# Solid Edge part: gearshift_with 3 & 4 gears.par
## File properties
Author: vinurabandara
Template: iso metric part.par
Last saved by: Nimesh.N
Revision: 22
Application: Solid Edge
Density: 7833.000 kg/m^3
Accuracy: 0.990
Username: Nimesh.N
Material: Steel
Face Style: Steel
Fill Style: ANSI32(Steel)
Virtual Style: Machined steel
Grouping: Metals\Steel
LibraryName: Materials
Coef. of Thermal Exp: 1.3e-05
Thermal Conductivity: 32.0
Specific Heat: 481.0
Modulus of Elasticity: 199947953000.0
Poisson's Ratio: 0.29
Yield Stress: 262000766.0
Ultimate Stress: 358527364.0
Elongation: 0.0
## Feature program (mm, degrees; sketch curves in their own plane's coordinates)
sketch for "unnamed Protrusion 1" plane through (0, 0, 0) normal (0, -1, 0) x-axis (1, 0, 0)
  line (-20, 111) -> (20, 111)
  line (20, 111) -> (68.5807, 62.4193)
  line (68.5807, 18.3762) -> (68.5807, 62.4193)
  line (53.6089, 14.3645) -> (68.5807, 18.3762)
  line (-53.6089, 14.3645) -> (-68.5807, 18.3762)
  line (-68.5807, 18.3762) -> (-68.5807, 62.4193)
  line (-20, 111) -> (-68.5807, 62.4193)
extrude "unnamed Protrusion 1" add finite 10 along +normal
fillet "Round_1" radius 10
sketch for "ExtrudedProtrusion_4" plane through (0, -5, 111) normal (0, 0, 1) x-axis (0, 1, 0)
extrude "ExtrudedProtrusion_4" add finite 250 along +normal
rib "Rib_2"  Thickness = 15 mm
fillet "Round_2" radius 5
fillet "Round_3" radius 5
sketch for "ExtrudedCutout_2" plane through (0, 0, 292) normal (0, 0, 1) x-axis (1, 0, 0)
extrude "ExtrudedCutout_2" cut finite 83 along +normal  Profile_Plane1_Distance = 292 mm
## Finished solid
Body 1: solid body, 20 faces, 54 edges, 36 vertices.
  Faces by surface: plane 15, cylinder 5
  Edges by curve: line 44, circle 10
Bounding box of the edges (mm): 137.161 x 15.000 x 277.635, from (-68.5807, -15, 14.3645) to (68.5807, 0, 292).
Cylindrical faces by radius (mm): R5 x2, R10 x2, R55.5 x1
Planar faces by outward normal: +x 2, +y 1, +z 3, -x 2, -y 2, oblique 5
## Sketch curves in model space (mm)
line (0, 0, 0) -> (0, 0, 158.5016)
line (68.5807, 0, 18.3762) -> (68.5807, 0, 62.4193)
line (20, 0, 111) -> (68.5807, 0, 62.4193)
line (-20, 0, 111) -> (20, 0, 111)
line (-20, 0, 111) -> (-68.5807, 0, 62.4193)
line (-68.5807, 0, 18.3762) -> (-68.5807, 0, 62.4193)
line (-53.6089, 0, 14.3645) -> (-68.5807, 0, 18.3762)
arc centre (0, 0, 0) radius 55.5 from (-53.6089, 0, 14.3645) through (1.6509, 0, 55.4754) to (53.6089, 0, 14.3645)
line (53.6089, 0, 14.3645) -> (68.5807, 0, 18.3762)
arc centre (0, 0, 0) radius 71 from (-68.5807, 0, 18.3762) through (2.1119, 0, 70.9686) to (68.5807, 0, 18.3762)
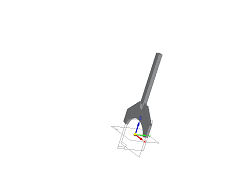
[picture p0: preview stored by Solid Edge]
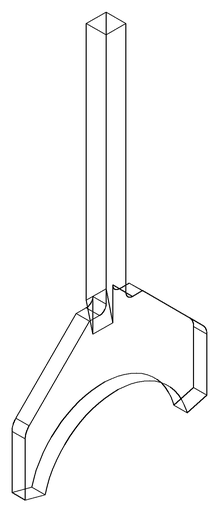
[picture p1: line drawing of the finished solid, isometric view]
